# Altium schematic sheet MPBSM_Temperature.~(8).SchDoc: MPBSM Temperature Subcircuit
size A3; Date: Not shown in title block; ApprovedBy: Not shown in title block; CheckedBy: Not shown in title block; Author: Not shown in title block; CompanyName: Not shown in title block; DrawnBy: Not shown in title block; Engineer: Not shown in title block; Organization: Not shown in title block; Address1: Not shown in title block; Address2: Not shown in title block; Address3: Not shown in title block; Address4: Not shown in title block; DocumentNumber: 11; Revision: Use project parameter SCH_Rev; SheetNumber: 11; SheetTotal: 12; PageSetup: Record=PageOptions¦CenterHorizontal=True¦CenterVertical=True¦PrintScale=0.69¦XCorrection=1.00¦YCorrection=1.00¦PrintKind=0¦BorderSize=5000000¦LeftOffset=0¦BottomOffset=0¦Orientation=2¦PaperLength=1000¦PaperWidth=1000¦Scale=100¦PaperSource=15¦PrintQuality=600¦MediaType=1¦DitherType=10¦PaperKind=Letter¦PrintScaleMode=1
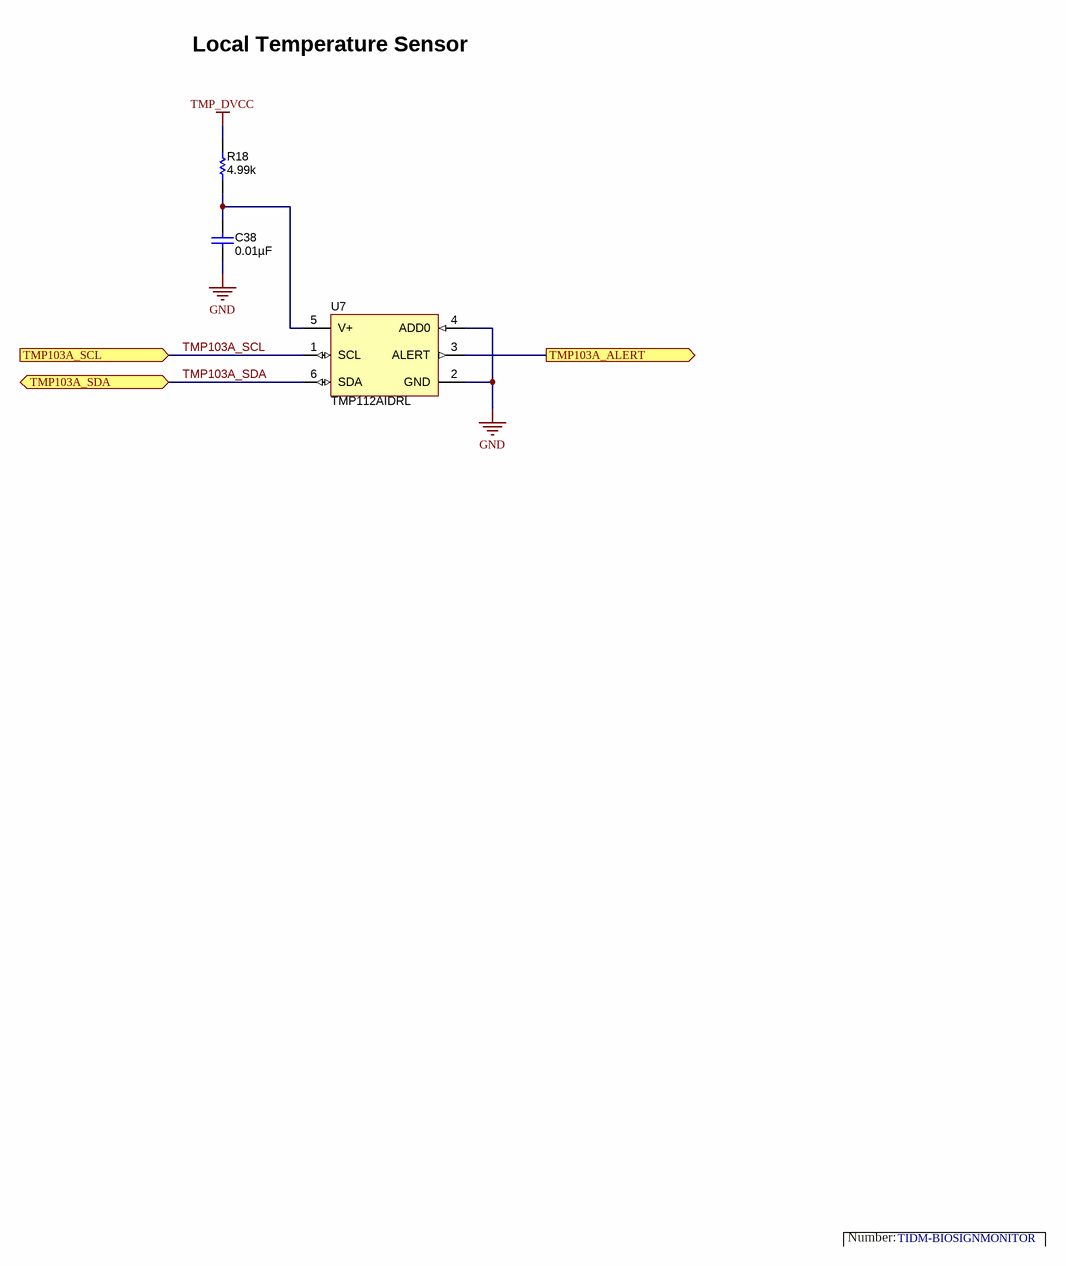
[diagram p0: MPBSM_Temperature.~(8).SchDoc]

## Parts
C38  ValueDisplayed: 0.01µF  [0402]  (hidden comment: C1005X7R1E103K)
R18  ValueDisplayed: 4.99k  [0402]  (hidden comment: CRCW04024K99FKED)
U7  TMP112AIDRL  [DRL0006A]

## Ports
TMP103A_ALERT (out), TMP103A_SCL (in), TMP103A_SDA (bidir)

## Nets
GND: C38.2 U7.2(GND) U7.4(ADD0)
TMP_DVCC: R18.2
TMP103A_ALERT: U7.3(ALERT) ; port TMP103A_ALERT
TMP103A_SCL: U7.1(SCL) ; port TMP103A_SCL
TMP103A_SDA: U7.6(SDA) ; port TMP103A_SDA
NetC38_1: C38.1 R18.1 U7.5(V+)

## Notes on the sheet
- Local Temperature Sensor
- Number:
- TIDM-BIOSIGNMONITOR

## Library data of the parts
C38 = C1005X7R1E103K: CAP, CERM, 0.01 µF, 25 V, +/- 10%, X7R, 0402; Manufacturer: TDK; Polarized: N; CompType: Capacitor; Value: 0.01uF; U/M: EA; Cap_F: 0.00000001; Tolerance_%: 10; ESR_ohm: 0.0623; Value1: 0.0623 ohm; VDC_V: 25; Value2: 25V; TaMin_C: -55; TaMax_C: 125
R18 = CRCW04024K99FKED: RES, 4.99 k, 1%, 0.063 W, 0402; Manufacturer: Vishay-Dale; CompType: Resistor; Value: 4.99k; Res_ohm: 4990; Value_Code: 4k99; Tolerance_%: 1; Power_W: 0.063; Value2: 0.063W; VDC_V: 50; TempCo: 100 ppm/C; EIA_Code: E96; U/M: EA
U7 = TMP112AIDRL: High-Accuracy, Low-Power, Digital Temperature Sensor With SMBus(TM)/Two-Wire Serial Interface, DRL0006A; Manufacturer: Texas Instruments; SymbolCreator: a0799628; CompType: IC; U/M: EA; SupplyCurrent: 10 uA; SupplyVoltage: 1.4 V - 3.6 V; SupplyVoltageMax_V: 3.6 V; SupplyVoltageMin_V: 1.4 V; TaMax_C: + 125 °C; TaMin_C: - 40 °C; Value: Mixed-Signal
